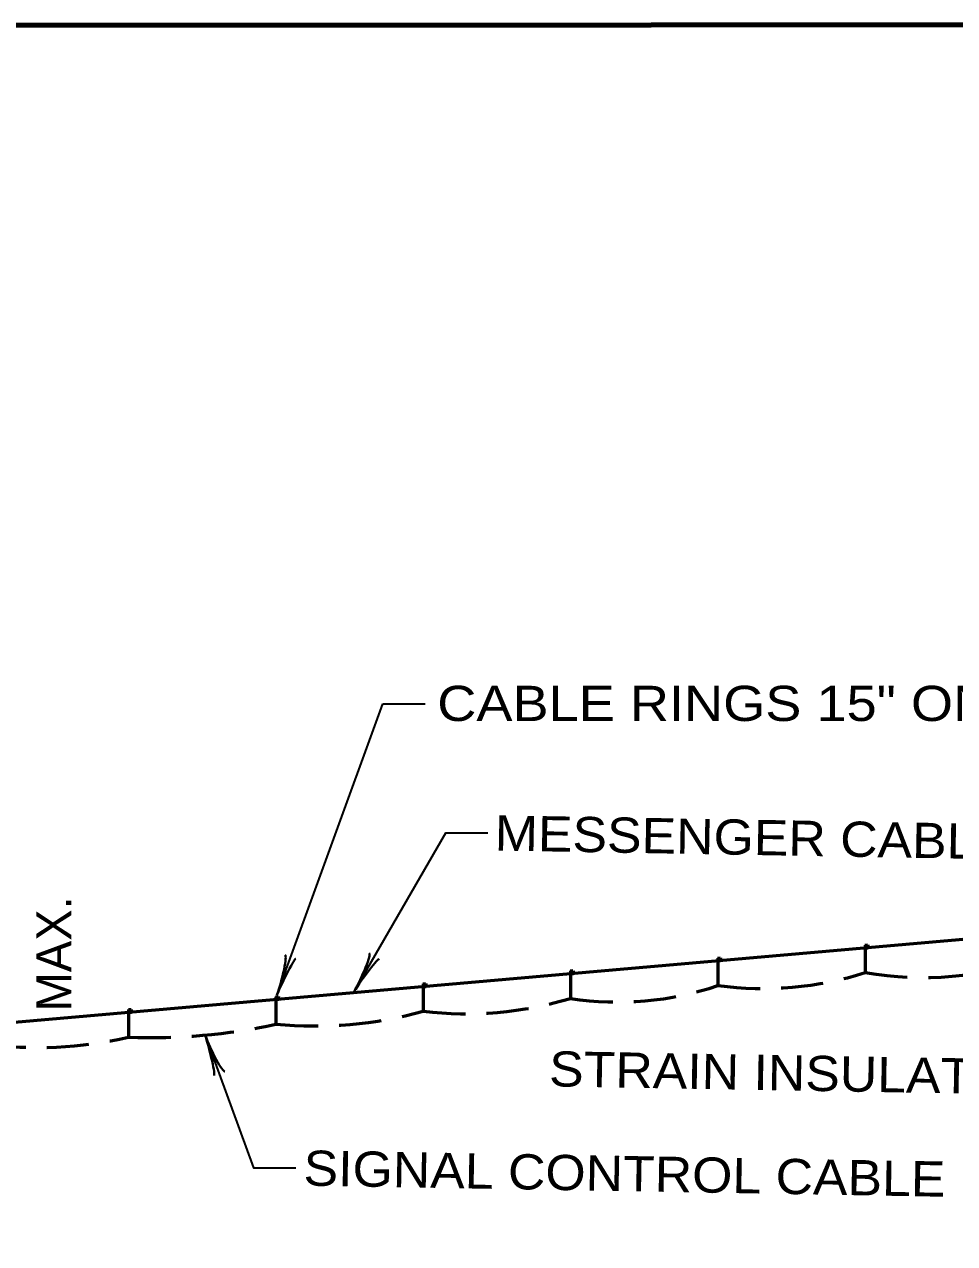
# Model space of a CAD drawing. Extents: x 14808 to 15663, y 10944 to 11488.
# Drawn here: x 15075.7 to 15154.9, y 11377.9 to 11481.7 of the extents above; entities that cross this region are included whole.
import ezdxf
from ezdxf.enums import TextEntityAlignment as Align

# ---------------------------------------------------------------- set-up
doc = ezdxf.new("R2010")
doc.units = 0
doc.header["$LTSCALE"] = 1.2
doc.linetypes.add('MEDIUM_DASHED', pattern=[4.5, 3, -1.5])
doc.layers.add('1', color=7, linetype='Continuous', lineweight=53)

msp = doc.modelspace()

# ---------------------------------------------------------------- linework, layer by layer
at = {"layer": '1', "lineweight": 35}
for p, q in [((15097.193, 11399.082), (15106.222, 11423.889)), ((15106.222, 11423.889), (15109.822, 11423.889))]:
    msp.add_line(p, q, dxfattribs=at)
at = {"layer": '1'}
for p, q in [((15158.822, 11404.102), (15074.187, 11396.698)), ((15147.297, 11403.335), (15147.536, 11403.355)), ((15147.297, 11403.335), (15147.318, 11403.095)), ((15147.302, 11403.275), (15147.482, 11403.29)), ((15147.302, 11403.275), (15147.318, 11403.095)), ((15147.313, 11403.336), (15147.334, 11403.097)), ((15147.318, 11403.095), (15147.557, 11403.116)), ((15147.318, 11403.095), (15147.497, 11403.111)), ((15147.319, 11403.276), (15147.334, 11403.097)), ((15147.332, 11403.338), (15147.352, 11403.099)), ((15147.337, 11403.278), (15147.352, 11403.099)), ((15147.35, 11403.339), (15147.371, 11403.1)), ((15147.355, 11403.279), (15147.371, 11403.1)), ((15147.368, 11403.341), (15147.389, 11403.102)), ((15147.373, 11403.281), (15147.389, 11403.102)), ((15147.377, 11403.342), (15147.398, 11403.103)), ((15147.39, 11403.343), (15147.411, 11403.104)), ((15147.395, 11403.283), (15147.411, 11403.104)), ((15147.404, 11403.344), (15147.424, 11403.105)), ((15147.409, 11403.284), (15147.424, 11403.105)), ((15147.417, 11403.345), (15147.437, 11403.106)), ((15147.427, 11403.346), (15147.447, 11403.107)), ((15147.432, 11403.286), (15147.447, 11403.107)), ((15147.445, 11403.347), (15147.465, 11403.108)), ((15147.45, 11403.288), (15147.465, 11403.108)), ((15147.462, 11403.349), (15147.483, 11403.11)), ((15147.468, 11403.289), (15147.483, 11403.11)), ((15147.477, 11403.35), (15147.497, 11403.111)), ((15147.482, 11403.29), (15147.497, 11403.111)), ((15147.49, 11403.351), (15147.51, 11403.112)), ((15147.501, 11403.352), (15147.522, 11403.113)), ((15147.513, 11403.353), (15147.534, 11403.114)), ((15147.525, 11403.354), (15147.546, 11403.115)), ((15147.536, 11403.355), (15147.557, 11403.116)), ((15134.745, 11402.236), (15134.984, 11402.257)), ((15134.745, 11402.236), (15134.766, 11401.997)), ((15134.761, 11402.238), (15134.782, 11401.999)), ((15134.779, 11402.239), (15134.8, 11402)), ((15134.798, 11402.241), (15134.818, 11402.002)), ((15134.816, 11402.243), (15134.837, 11402.003)), ((15134.825, 11402.243), (15134.846, 11402.004)), ((15134.838, 11402.245), (15134.859, 11402.005)), ((15134.851, 11402.246), (15134.872, 11402.007)), ((15134.864, 11402.247), (15134.885, 11402.008)), ((15134.874, 11402.248), (15134.895, 11402.009)), ((15134.892, 11402.249), (15134.913, 11402.01)), ((15134.91, 11402.251), (15134.931, 11402.012)), ((15134.924, 11402.252), (15134.945, 11402.013)), ((15134.937, 11402.253), (15134.958, 11402.014)), ((15134.949, 11402.254), (15134.97, 11402.015)), ((15134.961, 11402.255), (15134.982, 11402.016)), ((15134.973, 11402.256), (15134.994, 11402.017)), ((15134.984, 11402.257), (15135.005, 11402.018)), ((15147.318, 11403.095), (15147.318, 11400.995)), ((15122.193, 11401.138), (15122.432, 11401.159)), ((15122.193, 11401.138), (15122.214, 11400.899)), ((15122.198, 11401.078), (15122.378, 11401.094)), ((15122.198, 11401.078), (15122.214, 11400.899)), ((15122.209, 11401.14), (15122.23, 11400.901)), ((15122.214, 11401.08), (15122.23, 11400.901)), ((15122.227, 11401.141), (15122.248, 11400.902)), ((15122.233, 11401.081), (15122.248, 11400.902)), ((15122.246, 11401.143), (15122.266, 11400.904)), ((15122.251, 11401.083), (15122.266, 11400.904)), ((15122.264, 11401.144), (15122.284, 11400.905)), ((15122.269, 11401.085), (15122.284, 11400.905)), ((15122.273, 11401.145), (15122.294, 11400.906)), ((15122.286, 11401.146), (15122.307, 11400.907)), ((15122.291, 11401.087), (15122.307, 11400.907)), ((15122.299, 11401.147), (15122.32, 11400.908)), ((15122.305, 11401.088), (15122.32, 11400.908)), ((15122.312, 11401.149), (15122.333, 11400.909)), ((15122.322, 11401.149), (15122.343, 11400.91)), ((15122.328, 11401.09), (15122.343, 11400.91)), ((15122.34, 11401.151), (15122.361, 11400.912)), ((15122.346, 11401.091), (15122.361, 11400.912)), ((15122.358, 11401.153), (15122.379, 11400.914)), ((15122.363, 11401.093), (15122.379, 11400.914)), ((15122.372, 11401.154), (15122.393, 11400.915)), ((15122.378, 11401.094), (15122.393, 11400.915)), ((15122.385, 11401.155), (15122.406, 11400.916)), ((15122.397, 11401.156), (15122.418, 11400.917)), ((15122.409, 11401.157), (15122.43, 11400.918)), ((15122.421, 11401.158), (15122.442, 11400.919)), ((15122.432, 11401.159), (15122.453, 11400.92)), ((15134.766, 11401.997), (15134.945, 11402.013)), ((15134.766, 11401.997), (15134.766, 11399.897)), ((15109.641, 11400.04), (15109.88, 11400.061)), ((15109.641, 11400.04), (15109.662, 11399.801)), ((15109.646, 11399.98), (15109.825, 11399.996)), ((15109.657, 11400.041), (15109.678, 11399.802)), ((15109.675, 11400.043), (15109.696, 11399.804)), ((15109.693, 11400.045), (15109.714, 11399.805)), ((15109.699, 11399.985), (15109.714, 11399.805)), ((15109.711, 11400.046), (15109.732, 11399.807)), ((15109.717, 11399.986), (15109.732, 11399.807)), ((15109.721, 11400.047), (15109.742, 11399.808)), ((15109.734, 11400.048), (15109.754, 11399.809)), ((15109.739, 11399.988), (15109.754, 11399.809)), ((15109.747, 11400.049), (15109.768, 11399.81)), ((15109.752, 11399.989), (15109.768, 11399.81)), ((15109.76, 11400.05), (15109.781, 11399.811)), ((15109.77, 11400.051), (15109.791, 11399.812)), ((15109.775, 11399.992), (15109.791, 11399.812)), ((15109.788, 11400.053), (15109.809, 11399.814)), ((15109.793, 11399.993), (15109.809, 11399.814)), ((15109.806, 11400.054), (15109.827, 11399.815)), ((15109.811, 11399.995), (15109.827, 11399.815)), ((15109.82, 11400.056), (15109.841, 11399.817)), ((15109.825, 11399.996), (15109.841, 11399.817)), ((15109.833, 11400.057), (15109.854, 11399.818)), ((15109.845, 11400.058), (15109.866, 11399.819)), ((15109.857, 11400.059), (15109.878, 11399.82)), ((15109.869, 11400.06), (15109.89, 11399.821)), ((15109.88, 11400.061), (15109.901, 11399.822)), ((15122.214, 11400.899), (15122.453, 11400.92)), ((15122.214, 11400.899), (15122.393, 11400.915)), ((15122.214, 11400.899), (15122.214, 11398.799)), ((15097.093, 11398.943), (15097.332, 11398.964)), ((15097.145, 11398.948), (15097.166, 11398.709)), ((15097.163, 11398.949), (15097.184, 11398.71)), ((15097.173, 11398.95), (15097.193, 11398.711)), ((15097.185, 11398.951), (15097.206, 11398.712)), ((15097.199, 11398.952), (15097.22, 11398.713)), ((15097.212, 11398.954), (15097.233, 11398.715)), ((15097.222, 11398.954), (15097.243, 11398.716)), ((15097.24, 11398.956), (15097.261, 11398.717)), ((15097.258, 11398.958), (15097.279, 11398.719)), ((15097.272, 11398.959), (15097.293, 11398.72)), ((15097.285, 11398.96), (15097.306, 11398.721)), ((15097.297, 11398.961), (15097.317, 11398.722)), ((15097.309, 11398.962), (15097.329, 11398.723)), ((15097.321, 11398.963), (15097.341, 11398.724)), ((15097.332, 11398.964), (15097.353, 11398.725)), ((15109.646, 11399.98), (15109.662, 11399.801)), ((15109.662, 11399.982), (15109.678, 11399.802)), ((15109.662, 11399.801), (15109.901, 11399.822)), ((15109.662, 11399.801), (15109.841, 11399.817)), ((15109.662, 11399.801), (15109.662, 11397.701)), ((15109.68, 11399.983), (15109.696, 11399.804)), ((15097.093, 11398.943), (15097.113, 11398.704)), ((15097.098, 11398.883), (15097.277, 11398.899)), ((15097.098, 11398.883), (15097.113, 11398.704)), ((15097.109, 11398.945), (15097.13, 11398.706)), ((15097.113, 11398.704), (15097.353, 11398.725)), ((15097.113, 11398.704), (15097.293, 11398.72)), ((15097.113, 11398.704), (15097.113, 11396.604)), ((15097.114, 11398.885), (15097.13, 11398.706)), ((15097.127, 11398.946), (15097.148, 11398.707)), ((15097.132, 11398.886), (15097.148, 11398.707)), ((15097.15, 11398.888), (15097.166, 11398.709)), ((15097.168, 11398.89), (15097.184, 11398.71)), ((15097.19, 11398.891), (15097.206, 11398.712)), ((15097.204, 11398.893), (15097.22, 11398.713)), ((15097.227, 11398.895), (15097.243, 11398.716)), ((15097.245, 11398.896), (15097.261, 11398.717)), ((15097.263, 11398.898), (15097.279, 11398.719)), ((15097.277, 11398.899), (15097.293, 11398.72)), ((15084.537, 11397.844), (15084.776, 11397.864)), ((15084.537, 11397.844), (15084.558, 11397.604)), ((15084.542, 11397.784), (15084.721, 11397.799)), ((15084.542, 11397.784), (15084.558, 11397.604)), ((15084.553, 11397.845), (15084.574, 11397.606)), ((15084.558, 11397.785), (15084.574, 11397.606)), ((15084.558, 11397.604), (15084.797, 11397.625)), ((15084.558, 11397.604), (15084.737, 11397.62)), ((15084.558, 11397.604), (15084.558, 11395.504)), ((15084.571, 11397.847), (15084.592, 11397.608)), ((15084.576, 11397.787), (15084.592, 11397.608)), ((15084.589, 11397.848), (15084.61, 11397.609)), ((15084.594, 11397.788), (15084.61, 11397.609)), ((15084.607, 11397.85), (15084.628, 11397.611)), ((15084.612, 11397.79), (15084.628, 11397.611)), ((15084.617, 11397.851), (15084.638, 11397.612)), ((15084.629, 11397.852), (15084.65, 11397.613)), ((15084.635, 11397.792), (15084.65, 11397.613)), ((15084.643, 11397.853), (15084.664, 11397.614)), ((15084.648, 11397.793), (15084.664, 11397.614)), ((15084.656, 11397.854), (15084.677, 11397.615)), ((15084.666, 11397.855), (15084.687, 11397.616)), ((15084.671, 11397.795), (15084.687, 11397.616)), ((15084.684, 11397.856), (15084.705, 11397.617)), ((15084.689, 11397.797), (15084.705, 11397.617)), ((15084.702, 11397.858), (15084.723, 11397.619)), ((15084.707, 11397.798), (15084.723, 11397.619)), ((15084.716, 11397.859), (15084.737, 11397.62)), ((15084.721, 11397.799), (15084.737, 11397.62)), ((15084.729, 11397.86), (15084.75, 11397.621)), ((15084.741, 11397.861), (15084.761, 11397.622)), ((15084.753, 11397.862), (15084.774, 11397.623)), ((15084.765, 11397.863), (15084.785, 11397.624)), ((15084.776, 11397.864), (15084.797, 11397.625))]:
    msp.add_line(p, q, dxfattribs=at)
at = {"layer": '1', "lineweight": 158}
msp.add_lwpolyline([(15656.868, 11481.74), (14865.168, 11481.64), (14865.268, 10955.64)], dxfattribs=at)
at = {"layer": '1', "lineweight": 35}
for points in [[(15103.776, 11399.396), (15111.576, 11412.906), (15115.176, 11412.906)], [(15091.094, 11395.644), (15095.199, 11384.368), (15098.799, 11384.368)]]:
    msp.add_lwpolyline(points, dxfattribs=at)
at = {"layer": '1', "linetype": 'MEDIUM_DASHED'}
for centre, radius, start, end in [((15152.21, 11429.158), 28.584, 260.14661, 289.87015), ((15138.584, 11428.539), 28.895, 262.4067, 287.5936), ((15126.259, 11424.849), 26.362, 261.17367, 288.82663), ((15113.302, 11428.37), 30.885, 263.23016, 286.77014), ((15100.386, 11431.489), 35.038, 264.64029, 285.35034), ((15086.567, 11444.796), 49.332, 267.66564, 282.34434), ((15076.777, 11429.205), 34.587, 262.41333, 283)]:
    msp.add_arc(centre, radius, start, end, dxfattribs=at)
at = {"layer": '1', "lineweight": 40}
for centre, major_axis, ratio, start_param, end_param in [((15097.329, 11400.425), (-0.557, -2.078), 0.122415, 0.8963533, 3.1415927), ((15097.891, 11400.258), (0.919, 1.909), 0.07063, 6.2823074, 8.5597026), ((15104.143, 11400.696), (-0.909, -1.949), 0.122415, 0.8963533, 3.1415927), ((15104.668, 11400.433), (1.236, 1.72), 0.07063, 6.2823074, 8.5597026), ((15091.316, 11394.294), (0.523, -2.053), 0.07063, 6.2823074, 8.5597026), ((15091.854, 11394.527), (-0.909, 1.95), 0.122415, 0.8963533, 3.1415927)]:
    msp.add_ellipse(centre, major_axis=major_axis, ratio=ratio, start_param=start_param, end_param=end_param, dxfattribs=at)

# ---------------------------------------------------------------- texts
at = {"layer": '1', "width": 1.15}
msp.add_text('CABLE RINGS 15" ON CENTER', height=3, dxfattribs=at).set_placement((15110.853, 11422.418))
at = {"layer": '1', "width": 1.1}
for s, p in [('MESSENGER CABLE', (15115.733, 11411.392)), ('SIGNAL CONTROL CABLE', (15099.445, 11382.859))]:
    msp.add_text(s, height=3, rotation=359, dxfattribs=at).set_placement(p)
at = {"layer": '1'}
msp.add_text('MAX.', height=3, rotation=90, dxfattribs=at).set_placement((15079.688, 11402.588), align=Align.CENTER)
at = {"layer": '1', "width": 1.1}
msp.add_text('STRAIN INSULATOR', height=3, rotation=359, dxfattribs=at).set_placement((15163.022, 11390.566), align=Align.RIGHT)

doc.saveas('drawing.dxf')
